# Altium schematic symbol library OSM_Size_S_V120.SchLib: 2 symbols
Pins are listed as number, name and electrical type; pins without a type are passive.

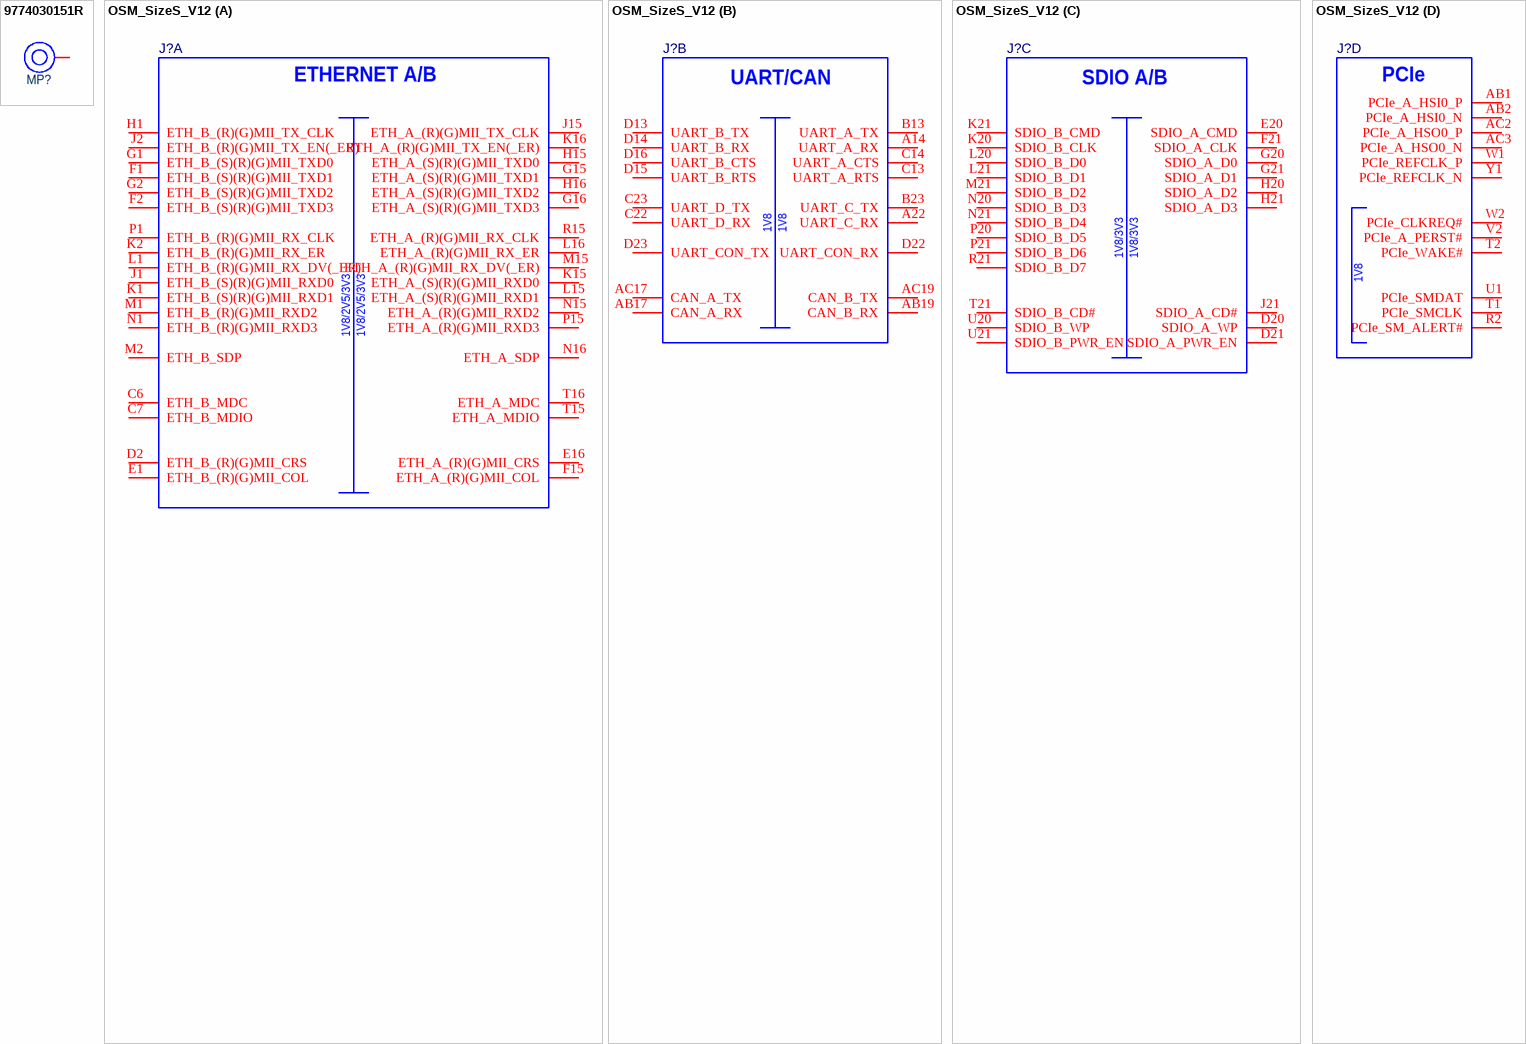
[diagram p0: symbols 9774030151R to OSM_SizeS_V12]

## 9774030151R
designator MP?, comment M2.5 x 3mm  (value not drawn)
WA-SMSI SMT Steel Spacer with internal Thread, OD 5.1mm, M2.5 x 3mm; Manufacturer Part Number: 9774030151R; Manufacturer: Wurth Elektronik; Inside Diameter: 3.5mm; Surface: Tin
footprint 9774030151
pins: 1

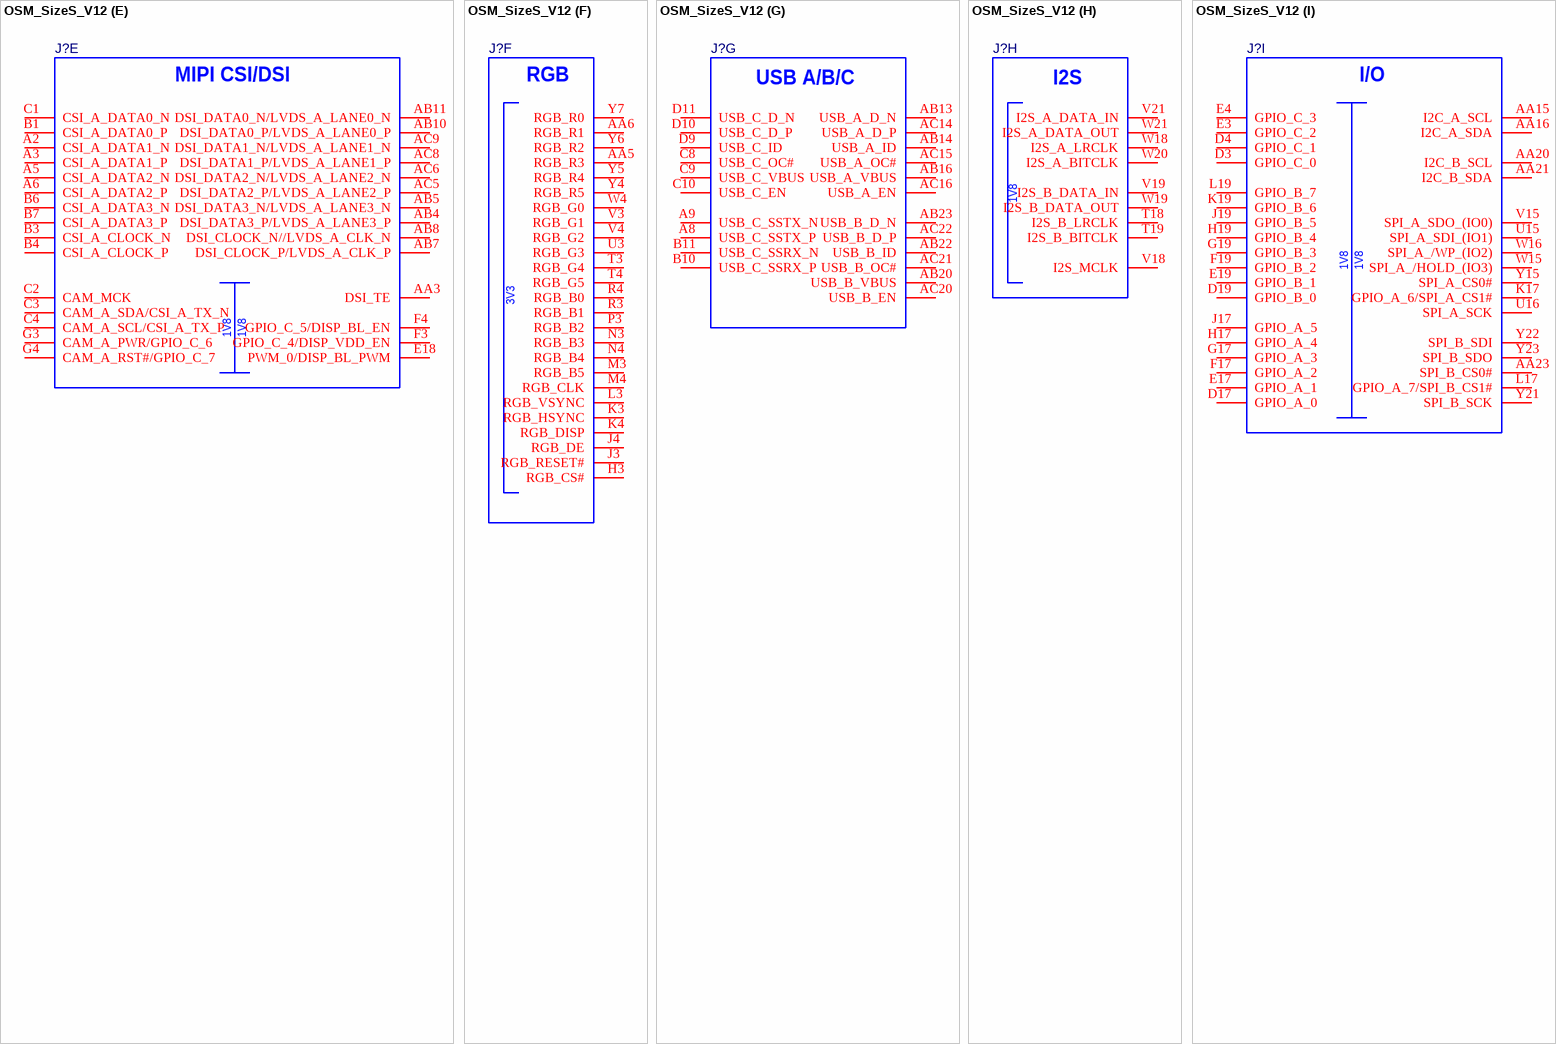
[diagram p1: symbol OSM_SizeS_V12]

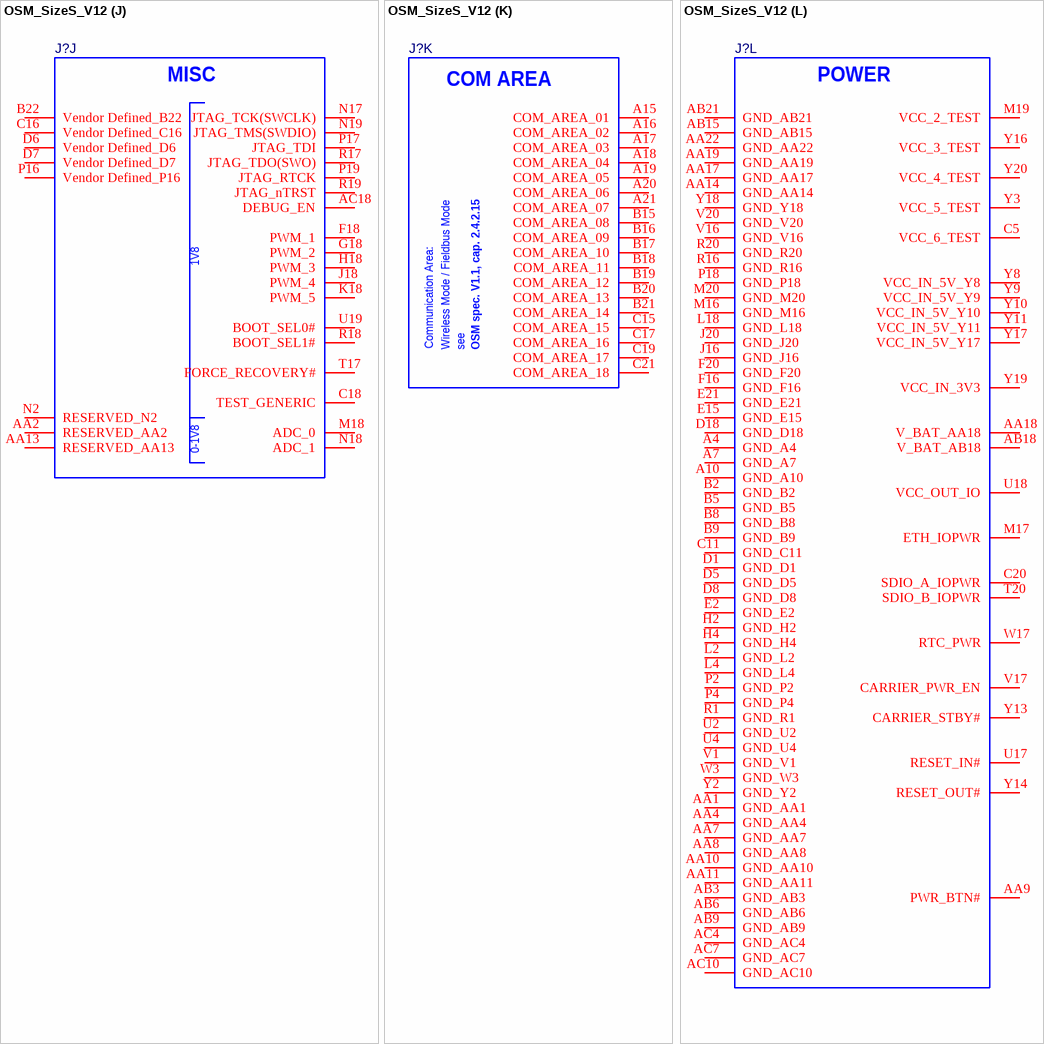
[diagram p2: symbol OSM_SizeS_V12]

## OSM_SizeS_V12
designator J?
part A pins: C6 ETH_B_MDC, C7 ETH_B_MDIO, D2 ETH_B_(R)(G)MII_CRS, E1 ETH_B_(R)(G)MII_COL, E16 ETH_A_(R)(G)MII_CRS, F1 ETH_B_(S)(R)(G)MII_TXD1, F2 ETH_B_(S)(R)(G)MII_TXD3, F15 ETH_A_(R)(G)MII_COL, G1 ETH_B_(S)(R)(G)MII_TXD0, G2 ETH_B_(S)(R)(G)MII_TXD2, G15 ETH_A_(S)(R)(G)MII_TXD1, G16 ETH_A_(S)(R)(G)MII_TXD3, H1 ETH_B_(R)(G)MII_TX_CLK, H15 ETH_A_(S)(R)(G)MII_TXD0, H16 ETH_A_(S)(R)(G)MII_TXD2, J1 ETH_B_(S)(R)(G)MII_RXD0, J2 ETH_B_(R)(G)MII_TX_EN(_ER), J15 ETH_A_(R)(G)MII_TX_CLK, K1 ETH_B_(S)(R)(G)MII_RXD1, K2 ETH_B_(R)(G)MII_RX_ER, K15 ETH_A_(S)(R)(G)MII_RXD0, K16 ETH_A_(R)(G)MII_TX_EN(_ER), L1 ETH_B_(R)(G)MII_RX_DV(_ER), L15 ETH_A_(S)(R)(G)MII_RXD1, L16 ETH_A_(R)(G)MII_RX_ER, M1 ETH_B_(R)(G)MII_RXD2, M2 ETH_B_SDP, M15 ETH_A_(R)(G)MII_RX_DV(_ER), N1 ETH_B_(R)(G)MII_RXD3, N15 ETH_A_(R)(G)MII_RXD2, N16 ETH_A_SDP, P1 ETH_B_(R)(G)MII_RX_CLK, P15 ETH_A_(R)(G)MII_RXD3, R15 ETH_A_(R)(G)MII_RX_CLK, T15 ETH_A_MDIO, T16 ETH_A_MDC
part B pins: A14 UART_A_RX, A22 UART_C_RX, AB17 CAN_A_RX, AB19 CAN_B_RX, AC17 CAN_A_TX, AC19 CAN_B_TX, B13 UART_A_TX, B23 UART_C_TX, C13 UART_A_RTS, C14 UART_A_CTS, C22 UART_D_RX, C23 UART_D_TX, D13 UART_B_TX, D14 UART_B_RX, D15 UART_B_RTS, D16 UART_B_CTS, D22 UART_CON_RX, D23 UART_CON_TX
part C pins: D20 SDIO_A_WP, D21 SDIO_A_PWR_EN, E20 SDIO_A_CMD, F21 SDIO_A_CLK, G20 SDIO_A_D0, G21 SDIO_A_D1, H20 SDIO_A_D2, H21 SDIO_A_D3, J21 SDIO_A_CD#, K20 SDIO_B_CLK, K21 SDIO_B_CMD, L20 SDIO_B_D0, L21 SDIO_B_D1, M21 SDIO_B_D2, N20 SDIO_B_D3, N21 SDIO_B_D4, P20 SDIO_B_D5, P21 SDIO_B_D6, R21 SDIO_B_D7, T21 SDIO_B_CD#, U20 SDIO_B_WP, U21 SDIO_B_PWR_EN
part D pins: AB1 PCIe_A_HSI0_P, AB2 PCIe_A_HSI0_N, AC2 PCIe_A_HSO0_P, AC3 PCIe_A_HSO0_N, R2 PCIe_SM_ALERT#, T1 PCIe_SMCLK, T2 PCIe_WAKE#, U1 PCIe_SMDAT, V2 PCIe_A_PERST#, W1 PCIe_REFCLK_P, W2 PCIe_CLKREQ#, Y1 PCIe_REFCLK_N
part E pins: A2 CSI_A_DATA1_N, A3 CSI_A_DATA1_P, A5 CSI_A_DATA2_N, A6 CSI_A_DATA2_P, AA3 DSI_TE, AB4 DSI_DATA3_P/LVDS_A_LANE3_P, AB5 DSI_DATA3_N/LVDS_A_LANE3_N, AB7 DSI_CLOCK_P/LVDS_A_CLK_P, AB8 DSI_CLOCK_N//LVDS_A_CLK_N, AB10 DSI_DATA0_P/LVDS_A_LANE0_P, AB11 DSI_DATA0_N/LVDS_A_LANE0_N, AC5 DSI_DATA2_P/LVDS_A_LANE2_P, AC6 DSI_DATA2_N/LVDS_A_LANE2_N, AC8 DSI_DATA1_P/LVDS_A_LANE1_P, AC9 DSI_DATA1_N/LVDS_A_LANE1_N, B1 CSI_A_DATA0_P, B3 CSI_A_CLOCK_N, B4 CSI_A_CLOCK_P, B6 CSI_A_DATA3_N, B7 CSI_A_DATA3_P, C1 CSI_A_DATA0_N, C2 CAM_MCK, C3 CAM_A_SDA/CSI_A_TX_N, C4 CAM_A_SCL/CSI_A_TX_P, E18 PWM_0/DISP_BL_PWM, F3 GPIO_C_4/DISP_VDD_EN, F4 GPIO_C_5/DISP_BL_EN, G3 CAM_A_PWR/GPIO_C_6, G4 CAM_A_RST#/GPIO_C_7
part F pins: AA5 RGB_R3, AA6 RGB_R1, H3 RGB_CS#, J3 RGB_RESET#, J4 RGB_DE, K3 RGB_HSYNC, K4 RGB_DISP, L3 RGB_VSYNC, M3 RGB_B5, M4 RGB_CLK, N3 RGB_B3, N4 RGB_B4, P3 RGB_B2, R3 RGB_B1, R4 RGB_B0, T3 RGB_G4, T4 RGB_G5, U3 RGB_G3, V3 RGB_G1, V4 RGB_G2, W4 RGB_G0, Y4 RGB_R5, Y5 RGB_R4, Y6 RGB_R2, Y7 RGB_R0
part G pins: A8 USB_C_SSTX_P, A9 USB_C_SSTX_N, AB13 USB_A_D_N, AB14 USB_A_ID, AB16 USB_A_VBUS, AB20 USB_B_VBUS, AB22 USB_B_ID, AB23 USB_B_D_N, AC14 USB_A_D_P, AC15 USB_A_OC#, AC16 USB_A_EN, AC20 USB_B_EN, AC21 USB_B_OC#, AC22 USB_B_D_P, B10 USB_C_SSRX_P, B11 USB_C_SSRX_N, C8 USB_C_OC#, C9 USB_C_VBUS, C10 USB_C_EN, D9 USB_C_ID, D10 USB_C_D_P, D11 USB_C_D_N
part H pins: T18 I2S_B_LRCLK, T19 I2S_B_BITCLK, V18 I2S_MCLK, V19 I2S_B_DATA_IN, V21 I2S_A_DATA_IN, W18 I2S_A_LRCLK, W19 I2S_B_DATA_OUT, W20 I2S_A_BITCLK, W21 I2S_A_DATA_OUT
part I pins: AA15 I2C_A_SCL, AA16 I2C_A_SDA, AA20 I2C_B_SCL, AA21 I2C_B_SDA, AA23 SPI_B_CS0#, D3 GPIO_C_0, D4 GPIO_C_1, D17 GPIO_A_0, D19 GPIO_B_0, E3 GPIO_C_2, E4 GPIO_C_3, E17 GPIO_A_1, E19 GPIO_B_1, F17 GPIO_A_2, F19 GPIO_B_2, G17 GPIO_A_3, G19 GPIO_B_3, H17 GPIO_A_4, H19 GPIO_B_4, J17 GPIO_A_5, J19 GPIO_B_5, K17 GPIO_A_6/SPI_A_CS1#, K19 GPIO_B_6, L17 GPIO_A_7/SPI_B_CS1#, L19 GPIO_B_7, U15 SPI_A_SDI_(IO1), U16 SPI_A_SCK, V15 SPI_A_SDO_(IO0), W15 SPI_A_/HOLD_(IO3), W16 SPI_A_/WP_(IO2), Y15 SPI_A_CS0#, Y21 SPI_B_SCK, Y22 SPI_B_SDI, Y23 SPI_B_SDO
part J pins: AA2 RESERVED_AA2, AA13 RESERVED_AA13, AC18 DEBUG_EN, B22 Vendor Defined_B22, C16 Vendor Defined_C16, C18 TEST_GENERIC, D6 Vendor Defined_D6, D7 Vendor Defined_D7, F18 PWM_1, G18 PWM_2, H18 PWM_3, J18 PWM_4, K18 PWM_5, M18 ADC_0, N2 RESERVED_N2, N17 JTAG_TCK(SWCLK), N18 ADC_1, N19 JTAG_TMS(SWDIO), P16 Vendor Defined_P16, P17 JTAG_TDI, P19 JTAG_RTCK, R17 JTAG_TDO(SWO), R18 BOOT_SEL1#, R19 JTAG_nTRST, T17 FORCE_RECOVERY#, U19 BOOT_SEL0#
part K pins: A15 COM_AREA_01, A16 COM_AREA_02, A17 COM_AREA_03, A18 COM_AREA_04, A19 COM_AREA_05, A20 COM_AREA_06, A21 COM_AREA_07, B15 COM_AREA_08, B16 COM_AREA_09, B17 COM_AREA_10, B18 COM_AREA_11, B19 COM_AREA_12, B20 COM_AREA_13, B21 COM_AREA_14, C15 COM_AREA_15, C17 COM_AREA_16, C19 COM_AREA_17, C21 COM_AREA_18
part L pins: A4 GND_A4 (power), A7 GND_A7 (power), A10 GND_A10 (power), AA1 GND_AA1 (power), AA4 GND_AA4 (power), AA7 GND_AA7 (power), AA8 GND_AA8 (power), AA9 PWR_BTN#, AA10 GND_AA10 (power), AA11 GND_AA11 (power), AA14 GND_AA14 (power), AA17 GND_AA17 (power), AA18 V_BAT_AA18, AA19 GND_AA19 (power), AA22 GND_AA22 (power), AB3 GND_AB3 (power), AB6 GND_AB6 (power), AB9 GND_AB9 (power), AB15 GND_AB15 (power), AB18 V_BAT_AB18, AB21 GND_AB21 (power), AC4 GND_AC4 (power), AC7 GND_AC7 (power), AC10 GND_AC10 (power), B2 GND_B2 (power), B5 GND_B5 (power), B8 GND_B8 (power), B9 GND_B9 (power), C5 VCC_6_TEST, C11 GND_C11 (power), C20 SDIO_A_IOPWR, D1 GND_D1 (power), D5 GND_D5 (power), D8 GND_D8 (power), D18 GND_D18 (power), E2 GND_E2 (power), E15 GND_E15 (power), E21 GND_E21 (power), F16 GND_F16 (power), F20 GND_F20 (power), H2 GND_H2 (power), H4 GND_H4 (power), J16 GND_J16 (power), J20 GND_J20 (power), L2 GND_L2 (power), L4 GND_L4 (power), L18 GND_L18 (power), M16 GND_M16 (power), M17 ETH_IOPWR (power), M19 VCC_2_TEST, M20 GND_M20 (power), P2 GND_P2 (power), P4 GND_P4 (power), P18 GND_P18 (power), R1 GND_R1 (power), R16 GND_R16 (power), R20 GND_R20 (power), T20 SDIO_B_IOPWR, U2 GND_U2 (power), U4 GND_U4 (power), U17 RESET_IN#, U18 VCC_OUT_IO, V1 GND_V1 (power), V16 GND_V16 (power), V17 CARRIER_PWR_EN, V20 GND_V20 (power), W3 GND_W3 (power), W17 RTC_PWR (power), Y2 GND_Y2 (power), Y3 VCC_5_TEST, Y8 VCC_IN_5V_Y8 (power), Y9 VCC_IN_5V_Y9 (power), Y10 VCC_IN_5V_Y10 (power), Y11 VCC_IN_5V_Y11 (power), Y13 CARRIER_STBY#, Y14 RESET_OUT#, Y16 VCC_3_TEST, Y17 VCC_IN_5V_Y17 (power), Y18 GND_Y18 (power), Y19 VCC_IN_3V3, Y20 VCC_4_TEST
